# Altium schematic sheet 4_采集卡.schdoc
size 307 x 218 mm; Symbol: Drawing-Symbol_A4; Device: Drawing-Symbol_A4; Company: 嘉立创EDA; Version: V1.0; Page Size: A4; @Project Name: New Project_2025-01-23_00-40-50; @Page Count: 4; @Update Date: 2025-08-15; @Create Date: 2025-07-30; @Schematic Name: Schematic3_7; @Page No: 4; @Page Name: 采集卡; @Create Time: 15:34:36; @Update Time: 14:29:42; Width: 1170; Height: 825; Region Start: 1; X Region Count: 6; Y Region Count: 4; Blade Width: 10; Title Block Position: 3; @Board Name: cm4
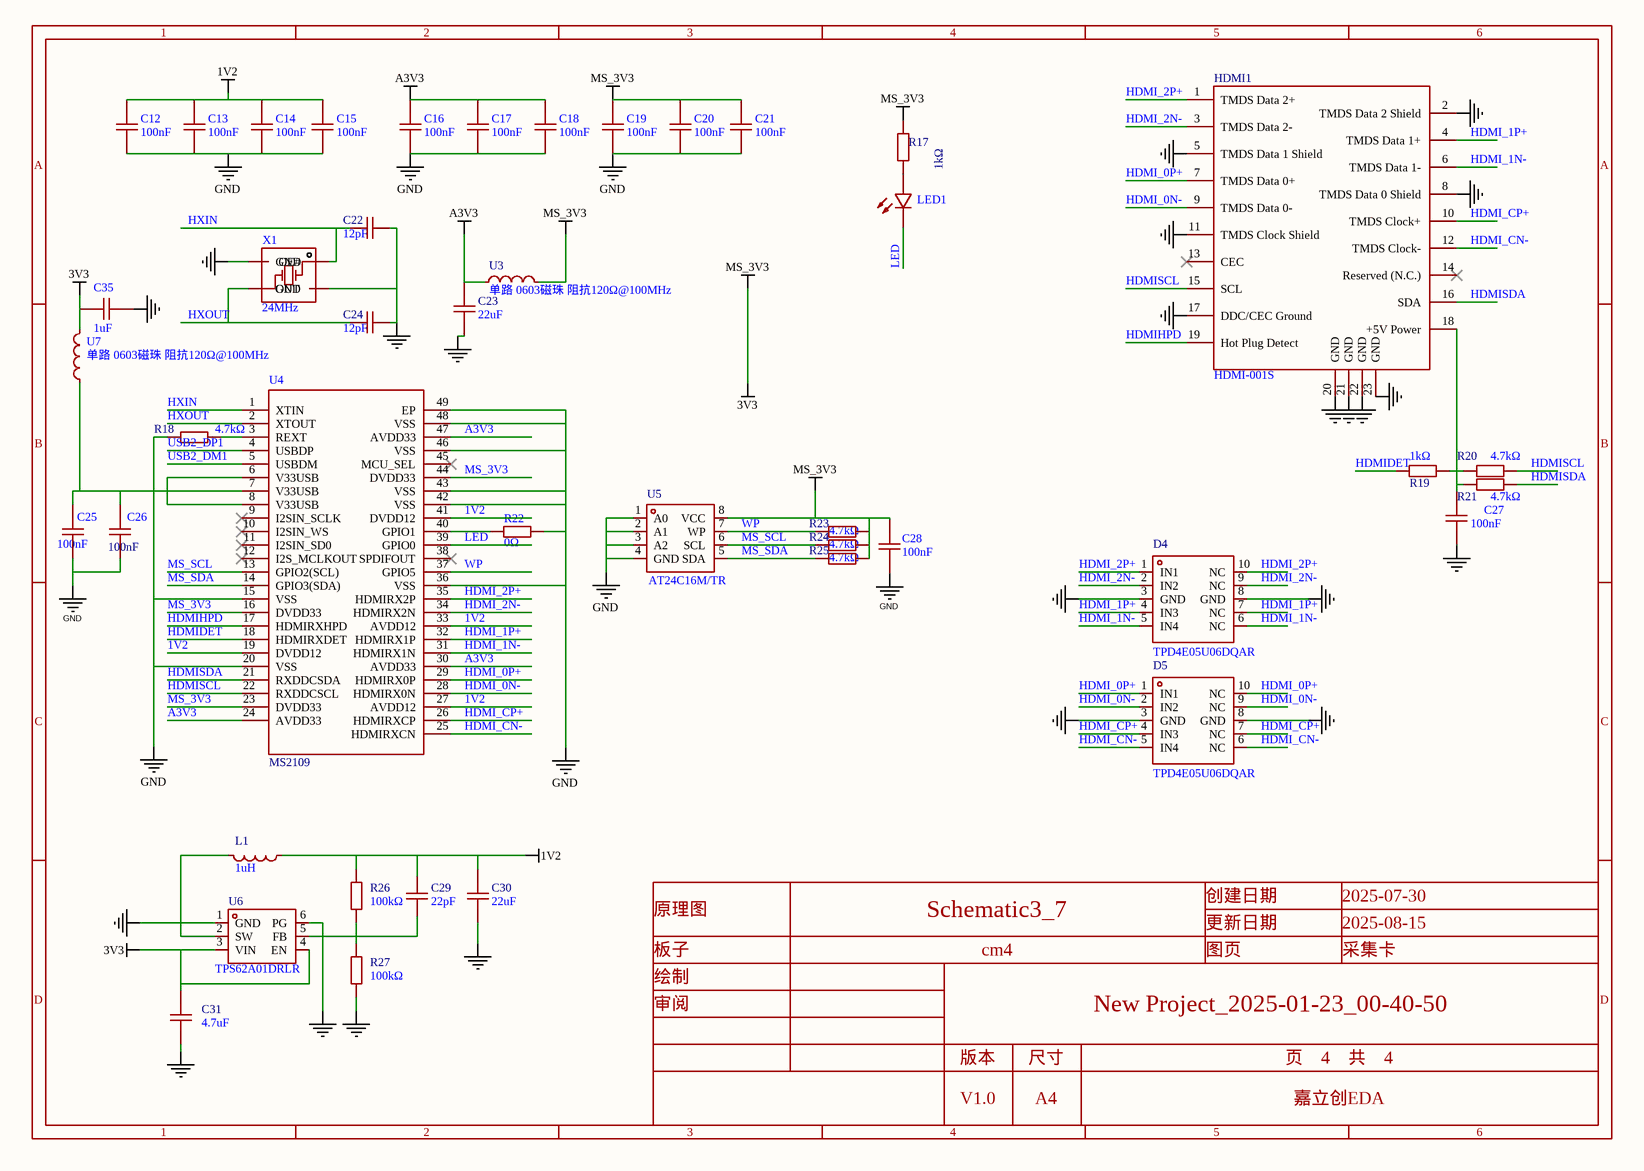
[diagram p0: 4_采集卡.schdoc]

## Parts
C12  100nF  [C0603]
C13  100nF  [C0603]
C14  100nF  [C0603]
C15  100nF  [C0603]
C16  100nF  [C0603]
C17  100nF  [C0603]
C18  100nF  [C0603]
C19  100nF  [C0603]
C20  100nF  [C0603]
C21  100nF  [C0603]
C22  12pF  [C0603]
C23  22uF  [C0603]
C24  12pF  [C0603]
C25  100nF  [C0603]
C26  100nF  [C0603]
C27  100nF  [C0603]
C28  100nF  [C0603]
C29  22pF  [C0603]
C30  22uF  [C0603]
C31  4.7uF  [C0603]
C35  1uF  [C0603]
D4  TPD4E05U06DQAR  [USON-10_L2.5-W1.0-P0.50-BL]
D5  TPD4E05U06DQAR  [USON-10_L2.5-W1.0-P0.50-BL]
HDMI1  HDMI-001S  [HDMI-SMD_HDMI-001S]
L1  1uH  [IND-SMD_L2.0-W1.6-B]
LED1  NCD0603R1  [LED0603-RD_RED]  (value not drawn)
R17  1kΩ  [R0603]
R18  4.7kΩ  [R0603]
R19  1kΩ  [R0603]
R20  4.7kΩ  [R0603]
R21  4.7kΩ  [R0603]
R22  0Ω  [R0603]
R23  4.7kΩ  [R0603]
R24  4.7kΩ  [R0603]
R25  4.7kΩ  [R0603]
R26  100kΩ  [R0603]
R27  100kΩ  [R0603]
U3  LCSC Part Name: 单路 0603磁珠 阻抗120Ω@100MHz  [L0603]  (hidden comment: BLM18PG121SN1D)
U4  MS2109  [QFN-48_L7.0-W7.0-P0.50-TL-EP4.1]
U5  (no value)  [SOP-8_L4.9-W3.9-P1.27-LS6.0-BL]
U6  TPS62A01DRLR  [SOT-5X3-6_L1.6-W1.2-P0.50-LS1.6-BR]
U7  LCSC Part Name: 单路 0603磁珠 阻抗120Ω@100MHz  [L0603]  (hidden comment: BLM18PG121SN1D)
X1  24MHz  [CRYSTAL-SMD_4P-L3.2-W2.5-BL]

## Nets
1V2: C12.2 C13.2 C14.2 C15.2 C29.2 C30.2 L1.1 R26.2 U4.19(DVDD12) U4.27(AVDD12) U4.33(AVDD12) U4.41(DVDD12)
A3V3: C16.2 C17.2 C18.2 C23.2 U3.1 U4.24(AVDD33) U4.30(AVDD33) U4.47(AVDD33)
GND: C12.1 C13.1 C14.1 C15.1 C16.1 C17.1 C18.1 C19.1 C20.1 C21.1 C22.2 C23.1 C24.2 C25.1 C26.1 C27.1 C28.1 C30.1 C31.1 C35.1 D4.3(GND) D4.8(GND) D5.3(GND) D5.8(GND) HDMI1.2(TMDS_Data_2_Shield) HDMI1.5(TMDS_Data_1_Shield) HDMI1.8(TMDS_Data_0_Shield) HDMI1.11(TMDS_Clock_Shield) HDMI1.17(DDC/CEC_Ground) HDMI1.20(GND) HDMI1.21(GND) HDMI1.22(GND) HDMI1.23(GND) R18.1 R22.2 R27.1 U4.15(VSS) U4.20(VSS) U4.36(VSS) U4.42(VSS) U4.43(VSS) U4.46(VSS) U4.48(VSS) U4.49(EP) U5.1(A0) U5.2(A1) U5.3(A2) U5.4(GND) U6.1(GND) U6.6(PG) X1.2(GND) X1.4(GND)
MS_3V3: C19.2 C20.2 C21.2 C28.2 C31.2 C35.2 R17.2 R23.2 R24.2 R25.2 U3.2 U4.16(DVDD33) U4.23(DVDD33) U4.44(DVDD33) U5.8(VCC) U6.3(VIN) U6.4(EN) U7.2  [also labelled 3V3]
HDMI_0N-: D5.2(IN2) D5.9(NC) HDMI1.9(TMDS_Data_0-) U4.28(HDMIRX0N)
HDMI_0P+: D5.1(IN1) D5.10(NC) HDMI1.7(TMDS_Data_0+) U4.29(HDMIRX0P)
HDMI_1N-: D4.5(IN4) D4.6(NC) HDMI1.6(TMDS_Data_1-) U4.31(HDMIRX1N)
HDMI_1P+: D4.4(IN3) D4.7(NC) HDMI1.4(TMDS_Data_1+) U4.32(HDMIRX1P)
HDMI_2N-: D4.2(IN2) D4.9(NC) HDMI1.3(TMDS_Data_2-) U4.34(HDMIRX2N)
HDMI_2P+: D4.1(IN1) D4.10(NC) HDMI1.1(TMDS_Data_2+) U4.35(HDMIRX2P)
HDMI_CN-: D5.5(IN4) D5.6(NC) HDMI1.12(TMDS_Clock-) U4.25(HDMIRXCN)
HDMI_CP+: D5.4(IN3) D5.7(NC) HDMI1.10(TMDS_Clock+) U4.26(HDMIRXCP)
HDMIDET: R19.1 U4.18(HDMIRXDET)
HDMIHPD: HDMI1.19(Hot_Plug_Detect) U4.17(HDMIRXHPD)
HDMISCL: HDMI1.15(SCL) R20.2 U4.22(RXDDCSCL)
HDMISDA: HDMI1.16(SDA) R21.2 U4.21(RXDDCSDA)
HXIN: C22.1 U4.1(XTIN) X1.1(OE#)
HXOUT: C24.1 U4.2(XTOUT) X1.3(OUT)
LED: LED1.1(K) U4.39(GPIO0)
MS_SCL: R24.1 U4.13(GPIO2(SCL)) U5.6(SCL)
MS_SDA: R25.1 U4.14(GPIO3(SDA)) U5.5(SDA)
USB2_DM1: U4.5(USBDM)
USB2_DP1: U4.4(USBDP)
WP: R23.1 U4.37(GPIO5) U5.7(WP)
NetC25_2: C25.2 C26.2 U4.6(V33USB) U4.7(V33USB) U4.8(V33USB) U7.1
NetC27_2: C27.2 HDMI1.18(+5V_Power) R19.2 R20.1 R21.1
NetC29_1: C29.1 R26.1 R27.2 U6.5(FB)
NetL1_2: L1.2 U6.2(SW)
NetLED1_2: LED1.2(A) R17.1
NetR18_2: R18.2 U4.3(REXT)
NetR22_1: R22.1 U4.40(GPIO1)

Not connected (* = marked no-connect by the designer): HDMI1 13(CEC)* 14(Reserved_(N.C.))*; U4 9(I2SIN_SCLK)* 10(I2SIN_WS)* 11(I2SIN_SD0)* 12(I2S_MCLKOUT)* 38(SPDIFOUT)* 45(MCU_SEL)*

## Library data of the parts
C12-C21 C25-C28 = CC0603KRX7R9BB104: Manufacturer: YAGEO(国巨); Symbol: CL05B104KO5NNNC; Add into BOM: yes; Tolerance: ±10%; Voltage Rated: 50V; Temperature Coefficient: X7R
C22 C24 = CL10C120JB8NNNC: Manufacturer: SAMSUNG(三星); Symbol: GRM1555C1H120JA01D; Add into BOM: yes; Tolerance: ±5%; Voltage Rated: 50V; Temperature Coefficient: C0G
C23 = CL10A226MQ8NRNC: Manufacturer: SAMSUNG(三星); Add into BOM: yes; Tolerance: ±20%; Voltage Rated: 6.3V; Temperature Coefficient: X5R
C29 = CL10C220JB8NNNC: Manufacturer: SAMSUNG(三星); Symbol: CC0402JRNPO9BN220; Add into BOM: yes; Tolerance: ±5%; Voltage Rated: 50V; Temperature Coefficient: C0G
C30 = CL10A226MQ8NRNC: Manufacturer: SAMSUNG(三星); Symbol: CGA0603X5R226M160JT; Add into BOM: yes; Tolerance: ±20%; Voltage Rated: 6.3V; Temperature Coefficient: X5R
C31 = CL10A475KO8NNNC: Manufacturer: SAMSUNG(三星); Symbol: CGA0603X5R226M160JT; Add into BOM: yes; Tolerance: ±10%; Voltage Rated: 16V; Temperature Coefficient: X5R
C35 = CL10A105KB8NNNC: Manufacturer: SAMSUNG(三星); Symbol: Capacitance; Add into BOM: yes; Tolerance: ±10%; Voltage Rated: 50V; Temperature Coefficient: X5R
D4 D5 = TPD4E05U06DQAR_C138714: Manufacturer: TI(德州仪器); Symbol: RClamp0524PATCT; Add into BOM: yes; polarity: 单向; Reverse Stand-Off Voltage (Vrwm): 5.5V; Maximum Clamping Voltage: 14V; Peak Pulse Current (Ipp)@10/1000us: 2.5A; Peak Pulse Power Dissipation (Ppp)@10/1000us: 40W; Breakdown Voltage: 6V; Number of Lines: 四路; Type: ESD
HDMI1 = HDMI-001S: Manufacturer: XUNPU(讯普); Add into BOM: yes; Connector Type: HDMI-A; Gender: 母
L1 = FTC201610S1R0MBCA: Manufacturer: cjiang(长江微电); Add into BOM: yes; Tolerance: ±20%; Rated Current: 4.5A; Saturation Current (Isat): 4.6A; DC Resistance (DCR): 35mΩ; Type: 一体成型电感
LED1 = NCD0603R1_C84263: Manufacturer: 国星光电; Symbol: FC-DA1608HRK-620D; Add into BOM: yes; Illumination Color: 红色; Voltage - Forward(Vf): 1.6V~2.6V; Power(Watts): 65mW; Forward Current: 25mA; Wavelength - Dominant: 615nm~630nm; Diode Configuration: 独立二极管; Luminous Intensity: 80mcd~220mcd; Viewing Angle: 130°
R17 R19 = 0603WAF1001T5E: Manufacturer: UNI-ROYAL(厚声); Symbol: 0402WGF1001TCE; Add into BOM: yes; Tolerance: ±1%; Power(Watts): 100mW; Overload Voltage (Max): 75V; Temperature Coefficient: ±100ppm/℃
R18 R23-R25 = 0603WAF4701T5E: Manufacturer: UNI-ROYAL(厚声); Symbol: 0402WGF4701TCE; Add into BOM: yes; Tolerance: ±1%; Power(Watts): 100mW; Overload Voltage (Max): 75V; Temperature Coefficient: ±100ppm/℃
R20 R21 = 0603WAF4701T5E: Manufacturer: UNI-ROYAL(厚声); Symbol: 0402WGF4702TCE; Add into BOM: yes; Tolerance: ±1%; Power(Watts): 100mW; Overload Voltage (Max): 75V; Temperature Coefficient: ±100ppm/℃
R22 = 0603WAF0000T5E: Manufacturer: UNI-ROYAL(厚声); Symbol: 0402WGF0000TCE; Add into BOM: yes; Tolerance: ±1%; Power(Watts): 100mW; Overload Voltage (Max): 75V
R26 = 0603WAF2003T5E: Manufacturer: UNI-ROYAL(厚声); Symbol: 0402WGF1003TCE; Add into BOM: yes; Tolerance: ±1%; Power(Watts): 100mW; Overload Voltage (Max): 75V; Temperature Coefficient: ±100ppm/℃
R27 = 0603WAF1003T5E: Manufacturer: UNI-ROYAL(厚声); Symbol: 0402WGF1003TCE; Add into BOM: yes; Tolerance: ±1%; Power(Watts): 100mW; Overload Voltage (Max): 75V; Temperature Coefficient: ±100ppm/℃
U3 U7 = BLM18PG121SN1D: Manufacturer: muRata(村田); Symbol: BLM18PG121SN1D_C14709; Add into BOM: yes; Impedance @ Frequency: 120Ω@100MHz; Tolerance: ±25%; DC Resistance: 50mΩ; Current Rating: 2A; Circuits: 1
U4 = MS2109: Add into BOM: yes; Origin Footprint: QFN48-7X7X05P; Check: false
U5 = AT24C16M/TR: Manufacturer: HGSEMI(华冠); Add into BOM: yes; Check: false
U6 = TPS62A01DRLR: Manufacturer: TI(德州仪器); Add into BOM: yes; Function: 降压型; Output Type: 可调; Input Voltage: 2.5V~5.5V; Output Voltage: 600mV~5.5V; Output Current: 1A; Switching Frequency: 2.4MHz; Synchronous Rectification: 是; Number of Outputs: 1; Topology: 降压式; Switch tube (built-in/external): 内置
X1 = TXM24M0004322FBCDO00T: Manufacturer: YJX(雅晶鑫); Symbol: SMD-3225_4P 24.000MHZ 12PF; Add into BOM: yes; Normal temperature Frequency Tolerance: ±10ppm; Load Capacitance: 12pF; Frequency Stability: ±20ppm; Equivalent Series Resistance(ESR): 30Ω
